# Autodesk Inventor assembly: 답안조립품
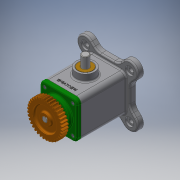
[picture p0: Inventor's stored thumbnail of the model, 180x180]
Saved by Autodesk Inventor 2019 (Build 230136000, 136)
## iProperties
Created: 2021-01
Part Number: 답안조립품
Material: 일반
Document SubType Name: Assembly
Designer: 3DPRO17
Author: 3DPRO17
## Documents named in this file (11)
- C:\Users\3DPRO17\Desktop\710114V1003\답안조립품.iam
- C:\Users\3DPRO17\Desktop\710114V1003\본체.ipt
- C:\Users\3DPRO17\Desktop\710114V1003\부시.ipt
- C:\Users\3DPRO17\Desktop\710114V1003\스퍼기어.ipt
- C:\Users\3DPRO17\Desktop\710114V1003\슬라이더.ipt
- C:\Users\3DPRO17\Desktop\710114V1003\오일 실.ipt
- C:\Users\3DPRO17\Desktop\710114V1003\커버.ipt
- C:\Users\3DPRO17\Desktop\710114V1003\키 4 x 4 x 14.ipt
- C:\Users\3DPRO17\Desktop\710114V1003\편심축.ipt
- C:\Users\3DPRO17\Desktop\710114V1003\베어링 6203.ipt
- C:\Users\3DPRO17\Desktop\710114V1003\볼트 M4.ipt
